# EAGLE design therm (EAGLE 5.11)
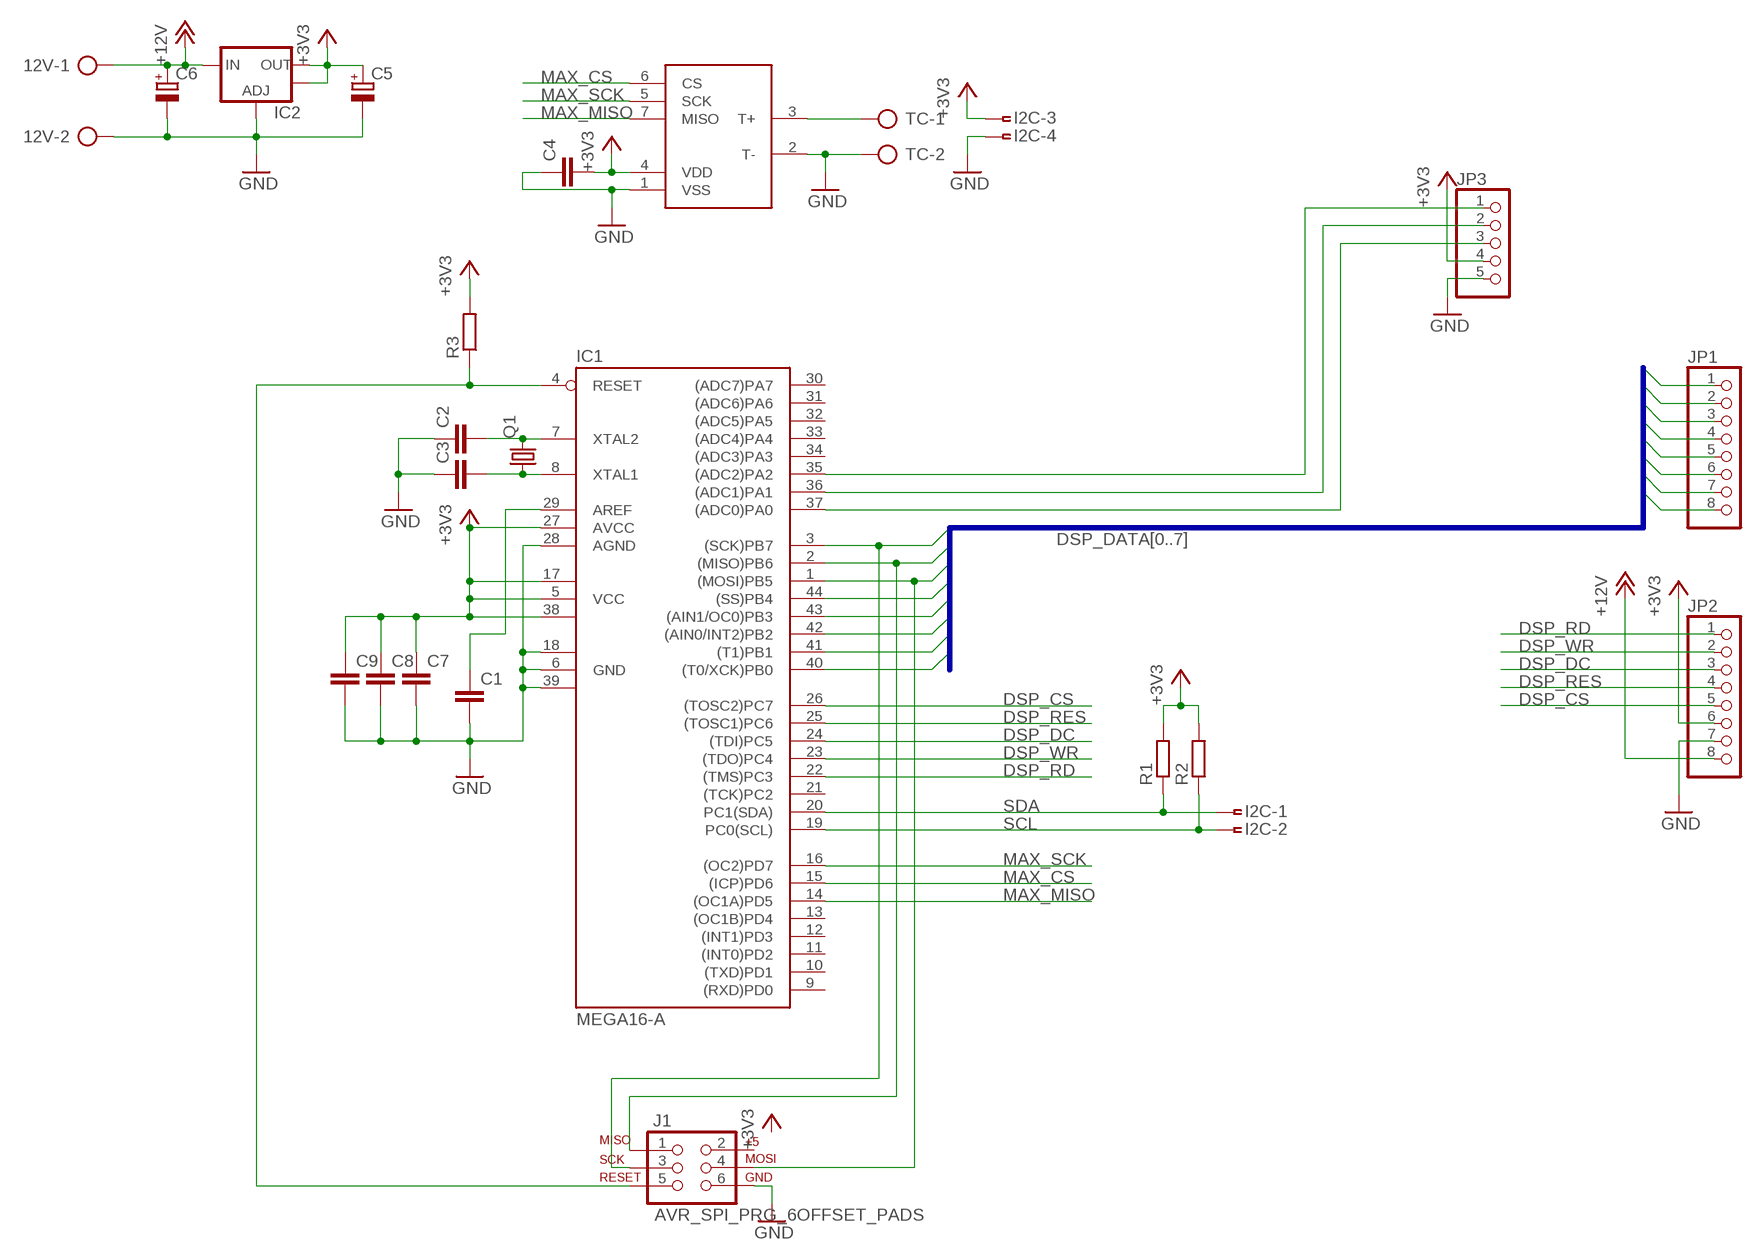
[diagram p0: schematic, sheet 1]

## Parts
12V  AK500/2  [AK500/2]
C1  C-EUC0603  [C0603]
C2  C-EUC0603  [C0603]
C3  C-EUC0603  [C0603]
C4  C-EUC0603  [C0603]
C5  CPOL-EU153CLV-0405  [153CLV-0405]
C6  CPOL-EU153CLV-0405  [153CLV-0405]
C7  C-EUC0603  [C0603]
C8  C-EUC0603  [C0603]
C9  C-EUC0603  [C0603]
I2C  SMDTOP-4  [SMDTOP4]
IC1  MEGA16-A  [TQFP44]
IC2  V_REG_LM1117SOT223  [SOT223]
IC3  MAX6675  [SO08]
J1  AVR_SPI_PRG_6OFFSET_PADS  [2X3_OFFSET]
JP1  PINHD-1X8  [1X08]
JP2  PINHD-1X8  [1X08]
JP3  PINHD-1X5/90  [1X05/90]
Q1  CRYSTALHC49U-V  [HC49U-V]
R1  R-EU_R0603  [R0603]
R2  R-EU_R0603  [R0603]
R3  R-EU_R1206  [R1206]
TC  AK500/2  [AK500/2]

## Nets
+3V3: C4.2 C5.+ C7.1 C8.1 C9.1 I2C.3 IC1.5(VCC) IC1.17(VCC1) IC1.27(AVCC) IC1.38(VCC2) IC2.2(OUT) IC2.4(OUT) IC3.4(VDD) JP2.6 JP3.4 R1.2 R2.2 R3.2
+12V: 12V.1 C6.+ IC2.3(IN) JP2.8
DSP_CS: IC1.26((TOSC2)PC7) JP2.5
DSP_DATA0: IC1.3((SCK)PB7) J1.3 JP1.1
DSP_DATA1: IC1.2((MISO)PB6) J1.1 JP1.2
DSP_DATA2: IC1.1((MOSI)PB5) J1.4 JP1.3
DSP_DATA3: IC1.44((SS)PB4) JP1.4
DSP_DATA4: IC1.43((AIN1/OC0)PB3) JP1.5
DSP_DATA5: IC1.42((AIN0/INT2)PB2) JP1.6
DSP_DATA6: IC1.41((T1)PB1) JP1.7
DSP_DATA7: IC1.40((T0/XCK)PB0) JP1.8
DSP_DC: IC1.24((TDI)PC5) JP2.3
DSP_RD: IC1.22((TMS)PC3) JP2.1
DSP_RES: IC1.25((TOSC1)PC6) JP2.4
DSP_WR: IC1.23((TDO)PC4) JP2.2
GND: 12V.2 C1.2 C2.1 C3.1 C4.1 C5.- C6.- C7.2 C8.2 C9.2 I2C.4 IC1.6(GND) IC1.18(GND1) IC1.28(AGND) IC1.39(GND2) IC2.1(ADJ) IC3.1(VSS) IC3.2(T-) J1.6 JP2.7 JP3.5 TC.2
MAX_CS: IC1.15((ICP)PD6) IC3.6(CS)
MAX_MISO: IC1.14((OC1A)PD5) IC3.7(MISO)
MAX_SCK: IC1.16((OC2)PD7) IC3.5(SCK)
N$1: C1.1 IC1.29(AREF)
N$2: C2.2 IC1.7(XTAL2) Q1.2
N$3: C3.2 IC1.8(XTAL1) Q1.1
N$6: IC1.35((ADC2)PA2) JP3.1
N$7: IC1.36((ADC1)PA1) JP3.2
N$8: IC1.37((ADC0)PA0) JP3.3
N$9: IC3.3(T+) TC.1
RESET: IC1.4(RESET) J1.5 R3.1
SCL: I2C.2 IC1.19(PC0(SCL)) R2.1
SDA: I2C.1 IC1.20(PC1(SDA)) R1.1
Unconnected: IC1.9((RXD)PD0) IC1.10((TXD)PD1) IC1.11((INT0)PD2) IC1.12((INT1)PD3) IC1.13((OC1B)PD4) IC1.21((TCK)PC2) IC1.30((ADC7)PA7) IC1.31((ADC6)PA6) IC1.32((ADC5)PA5) IC1.33((ADC4)PA4) IC1.34((ADC3)PA3) J1.2

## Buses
DSP_DATA[0..7]

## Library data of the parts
12V TC = con-ptr500:AK500/2: CONNECTOR; OC_FARNELL: unknown; OC_NEWARK: unknown
C1-C4 C7-C9 = rcl:C-EU: CAPACITOR, European symbol
C5 C6 = rcl:CPOL-EU: POLARIZED CAPACITOR, European symbol
I2C = con-amp2:SMDTOP-4: AMP connector
IC1 = avr-6:MEGA16: MICROCONTROLLER 16 Kbytes FLASH 1 kbytes SRAM 512 bytes EEPROM USART 8-channel 10 bit ADC
IC2 = SparkFun:V_REG_LM1117: Voltage Regulator LM1117 Standard adjustable voltage regulator but in SMD form. Spark Fun Electronics SKU : COM-00595
IC3 = max6675:MAX6675
J1 = SparkFun:AVR_SPI_PRG_6: AVR ISP 6 Pin This is the reduced ISP connector for AVR programming. Common on Arduino. This footprint will take up less PCB space and can be used with a 10-pin to 6-pin adapter such as SKU: BOB-08508
JP1 JP2 = pinhead:PINHD-1X8: PIN HEADER
JP3 = pinhead:PINHD-1X5: PIN HEADER
Q1 = crystal:CRYSTAL: CRYSTAL; OC_FARNELL: 1666969; OC_NEWARK: unknown
R1-R3 = rcl:R-EU_: RESISTOR, European symbol

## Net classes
0 default: clearance 0.254 mm

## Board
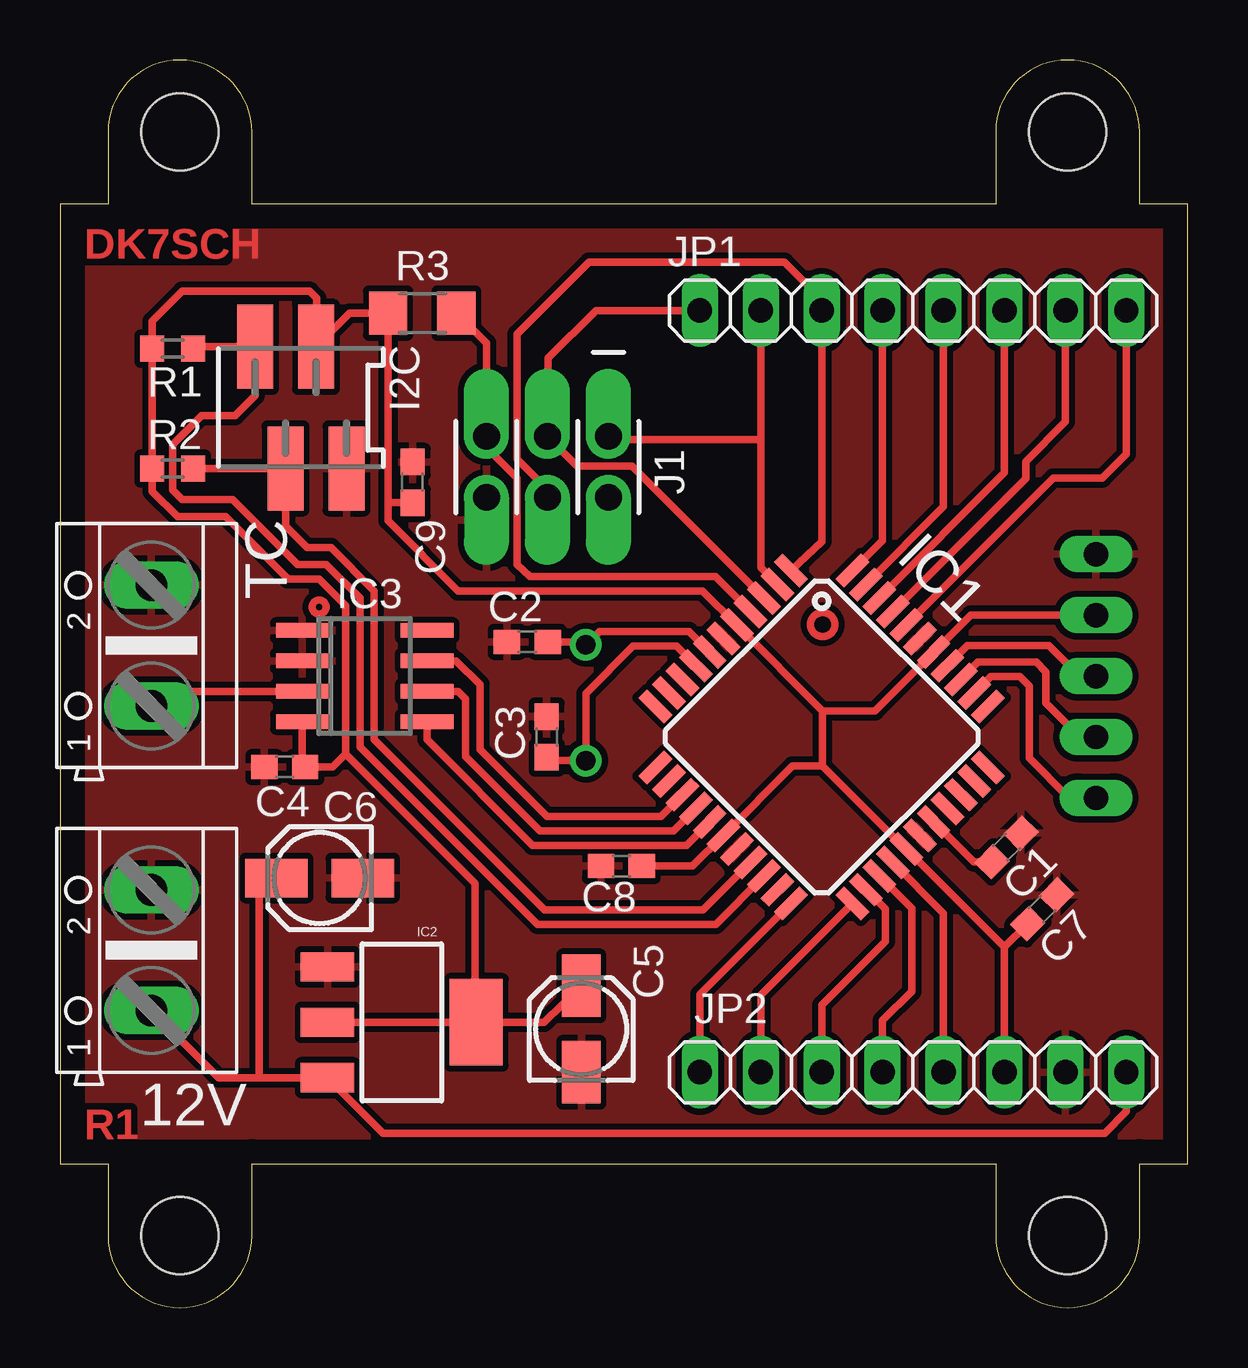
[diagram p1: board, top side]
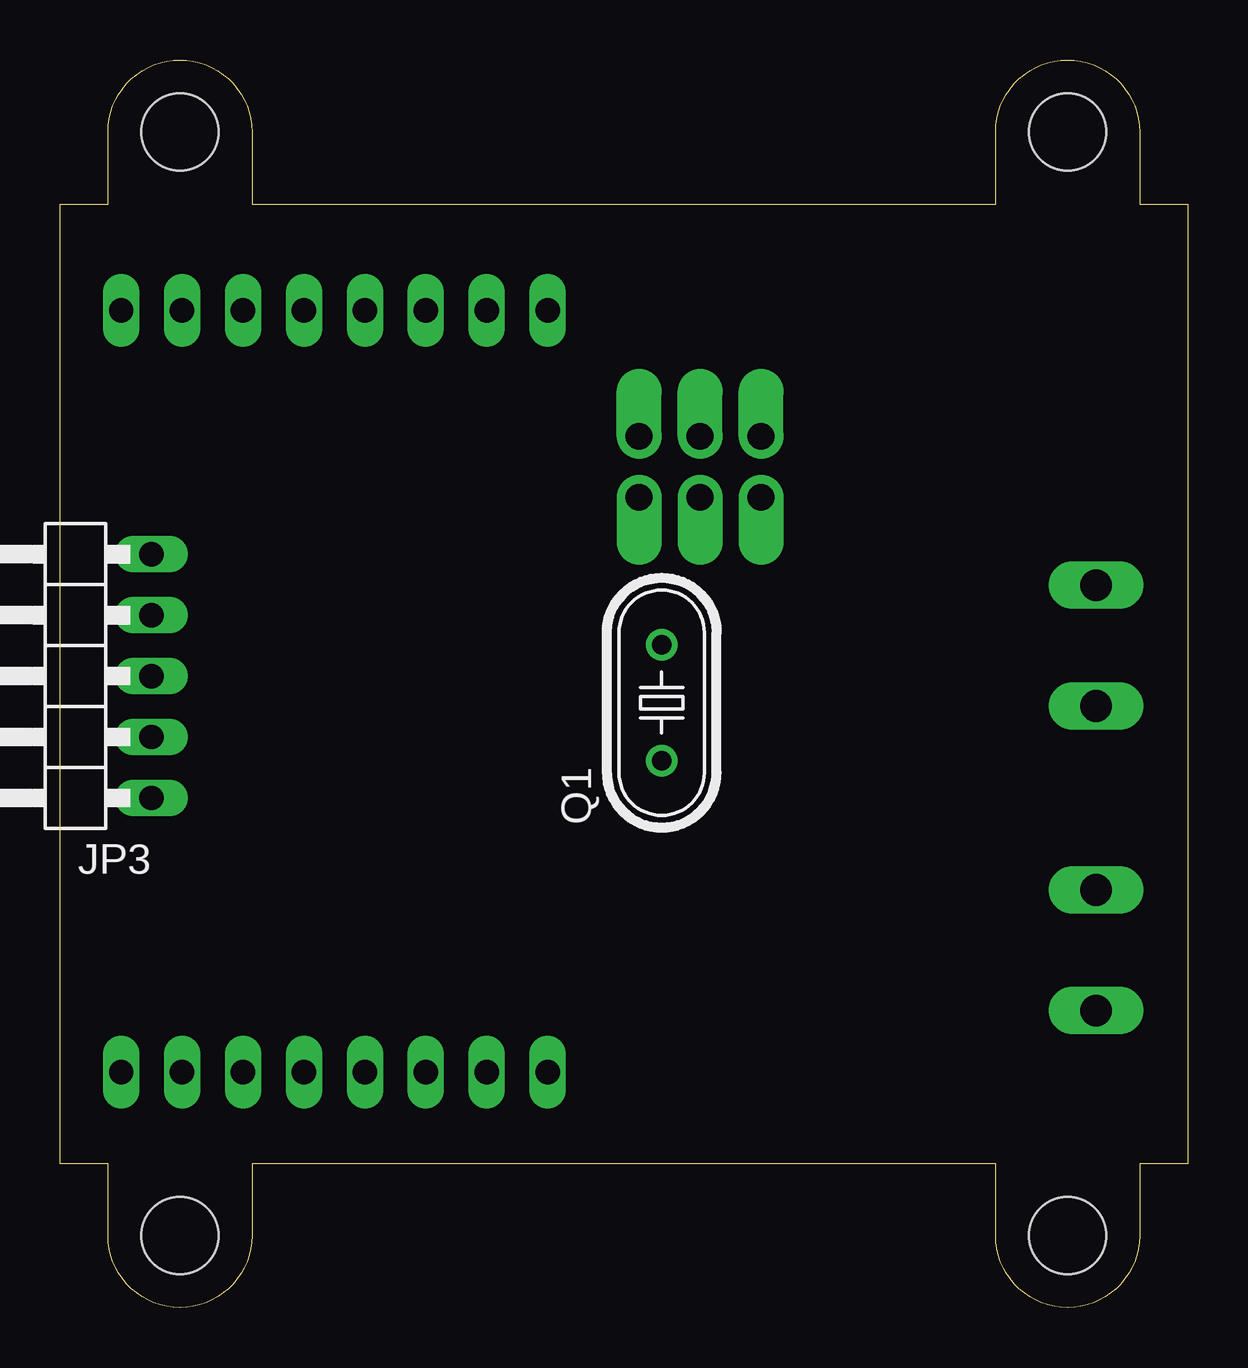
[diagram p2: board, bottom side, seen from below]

Size 47 x 52 mm. Coordinates in mm from the lower left corner, seen from the top.
Outline: 0,6 2,6 2,3 arc90 5,0 arc90 8,3 8,6 39,6 39,3 arc90 42,0 arc90 45,3 45,6 47,6 47,46 45,46 45,49 arc90 42,52 arc90 39,49 39,46 8,46 8,49 arc90 5,52 arc90 2,49 2,46 0,46 0,6
Copper layers (1*16): Top 0.035mm / dielectric 1.5mm / Bottom 0.035mm
Design rules "default": minimum track width 10mil, minimum drill 24mil, track to track 8mil, track to pad 8mil, pad to pad 8mil, via to via 8mil, smd to smd 8mil, copper to edge 40mil, drill to drill 8mil, minimum pad ring 10mil, minimum via ring 8mil, stop-mask expansion 4mil, vias tented up to drill 0mil, thermal gap 10mil
Holes 3.2 mm at 5,3 42,3 42,49 5,49
tRestrict: area 2,5 to 8,7; area 39,5 to 45,7; area 39,45 to 45,47; area 2,45 to 8,47

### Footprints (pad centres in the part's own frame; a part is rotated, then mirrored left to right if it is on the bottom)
AK500/2 = drill 1.321 long: 1 -2.515,0; 2 2.515,0
C0603 = smd 1.1 x 1: 1 -0.85,0; 2 0.85,0
153CLV-0405 = smd 2.6 x 1.6: + 1.8,0; - -1.8,0
SMDTOP4 = smd 1.5 x 3.5: 1 -1.905,2.54; 2 -0.635,-2.54; 3 0.635,2.54; 4 1.905,-2.54
TQFP44 = smd 1.5 x 0.5: 1 -5.8,4; 2 -5.8,3.2; 3 -5.8,2.4; 4 -5.8,1.6; 5 -5.8,0.8; 6 -5.8,0; 7 -5.8,-0.8; 8 -5.8,-1.6; 9 -5.8,-2.4; 10 -5.8,-3.2; 11 -5.8,-4; 23 5.8,-4; 24 5.8,-3.2; 25 5.8,-2.4; 26 5.8,-1.6; 27 5.8,-0.8; 28 5.8,0; 29 5.8,0.8; 30 5.8,1.6; 31 5.8,2.4; 32 5.8,3.2; 33 5.8,4 | smd 0.5 x 1.5: 12 -4,-5.8; 13 -3.2,-5.8; 14 -2.4,-5.8; 15 -1.6,-5.8; 16 -0.8,-5.8; 17 0,-5.8; 18 0.8,-5.8; 19 1.6,-5.8; 20 2.4,-5.8; 21 3.2,-5.8; 22 4,-5.8; 34 4,5.8; 35 3.2,5.8; 36 2.4,5.8; 37 1.6,5.8; 38 0.8,5.8; 39 0,5.8; 40 -0.8,5.8; 41 -1.6,5.8; 42 -2.4,5.8; 43 -3.2,5.8; 44 -4,5.8
SOT223 = smd 1.219 x 2.235: 1 -2.311,-3.099; 2 0,-3.099; 3 2.311,-3.099 | smd 3.6 x 2.2: 4 0,3.099
SO08 = smd 0.6 x 2.2: 1 -1.905,-2.6; 2 -0.635,-2.6; 3 0.635,-2.6; 4 1.905,-2.6; 5 1.905,2.6; 6 0.635,2.6; 7 -0.635,2.6; 8 -1.905,2.6
2X3_OFFSET = drill 1.118 pad 1.88 offset: 1 -2.54,-1.27; 2 -2.54,1.27; 3 0,-1.27; 4 0,1.27; 5 2.54,-1.27; 6 2.54,1.27
1X08 = drill 1.016 long: 1 -8.89,0; 2 -6.35,0; 3 -3.81,0; 4 -1.27,0; 5 1.27,0; 6 3.81,0; 7 6.35,0; 8 8.89,0
1X05/90 = drill 1.016 long: 1 -5.08,-3.81; 2 -2.54,-3.81; 3 0,-3.81; 4 2.54,-3.81; 5 5.08,-3.81
HC49U-V = drill 0.813 round: 1 -2.413,0; 2 2.413,0
R0603 = smd 1 x 1.1: 1 -0.85,0; 2 0.85,0
R1206 = smd 1.6 x 1.803: 1 -1.422,0; 2 1.422,0

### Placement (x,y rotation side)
12V  3.81,14.89 90 top
C1  39.45,19.18 45 top
C2  19.48,27.75 0 top
C3  20.29,23.78 270 top
C4  9.37,22.53 0 top
C5  21.73,11.61 90 top
C6  10.82,17.9 180 top
C7  40.94,16.6 45 top
C8  23.4,18.4 180 top
C9  14.7,34.4 90 top
I2C  10.04,37.51 0 top
IC1  31.75,23.78 315 top
IC2  14.25,11.89 270 top
IC3  12.7,26.32 270 top
J1  20.32,35.04 180 top
JP1  35.56,41.56 0 top
JP2  35.56,9.81 0 top
JP3  46.99,26.32 90 bottom
Q1  21.92,25.21 90 bottom
R1  4.7,39.97 180 top
R2  4.7,34.97 180 top
R3  15.1,41.45 180 top
TC  3.81,27.59 90 top

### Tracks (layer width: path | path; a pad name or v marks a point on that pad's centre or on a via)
+3V3
  Top 0.305: IC2.2 IC2.4 | 31.79,24.87 IC1.5 26.79,29.87 16.6,29.87 13.68,32.79 13.68,33.5 13.68,33.55 | 31.79,24.87 31.79,22.57 | 31.79,22.57 35.25,19.11 IC1.27 39.37,15.03 | 31.79,24.87 33.97,24.87 IC1.38 37.96,28.86 JP3.4 | 31.79,22.57 30.54,22.57 IC1.17 26.37,18.4 C8.1 | C5.+ 20.17,11.89 IC2.4 | 11.9,23.07 11.9,29.27 10.8,30.37 9.5,30.37 6.9,32.97 4.9,32.97 3.85,34.02 R2.2 R1.2 3.85,41.12 5.1,42.37 10.4,42.37 10.7,42.07 10.7,40.08 I2C.3 12.07,41.45 R3.2 13.68,33.55 | 11.9,23.07 17.3,17.67 17.3,11.94 IC2.4 | IC3.4 10.1,22.65 C4.2 11.36,22.53 11.9,23.07 | 39.37,15.03 JP2.6 | C7.1 | 39.37,15.03 C7.1 | 13.68,33.55 C9.1
+12V
  Top 0.305: JP2.8 44.45,8.17 43.55,7.27 13.46,7.27 IC2.3 8.3,9.58 | 3.8,12.37 12V.1 6.61,9.58 8.3,9.58 | C6.+ 8.3,17.18 8.3,9.58
DSP_CS
  Top 0.305: IC1.26 36.83,16.44 JP2.5
DSP_DATA0
  Top 0.305: JP1.1 22.34,41.56 20.35,39.57 20.35,36.34 J1.3 21.55,35.07 23.85,35.07 IC1.3
DSP_DATA1
  Top 0.305: IC1.2 29.21,30.84 29.21,36.17 | 29.21,36.17 JP1.2 | J1.1 23,36.17 29.21,36.17
DSP_DATA2
  Top 0.305: IC1.1 31.75,31.92 JP1.3 31.75,42.02 30.2,43.57 22.05,43.57 19.05,40.57 19.05,35.37 20.32,34.1 J1.4
DSP_DATA3
  Top 0.305: IC1.44 34.29,31.98 JP1.4
DSP_DATA4
  Top 0.305: IC1.43 36.83,33.39 JP1.5
DSP_DATA5
  Top 0.305: IC1.42 39.37,34.79 JP1.6
DSP_DATA6
  Top 0.305: JP1.7 41.91,36.93 40.25,35.27 40.25,34.54 IC1.41
DSP_DATA7
  Top 0.305: JP1.8 44.45,35.57 43.45,34.57 41.41,34.57 IC1.40
DSP_DC
  Top 0.305: IC1.24 34.4,16.6 34.4,15.27 31.75,12.62 JP2.3
DSP_RD
  Top 0.305: IC1.22 26.67,13.04 JP2.1
DSP_RES
  Top 0.305: IC1.25 35.5,16.64 35.5,13.17 34.29,11.96 JP2.4
DSP_WR
  Top 0.305: IC1.23 29.21,13.04 JP2.2
GND
  pour Top: 0,6 47,6 47,46 0,46
MAX_CS
  Top 0.305: IC1.15 25.58,19.87 20,19.87 16.9,22.97 16.9,25.37 16.59,25.68 IC3.6
MAX_MISO
  Top 0.305: IC1.14 25.05,20.47 20.3,20.47 17.5,23.27 17.5,25.97 16.52,26.95 IC3.7
MAX_SCK
  Top 0.305: IC1.16 26.11,19.27 19.7,19.27 15.3,23.67 IC3.5
N$1
  Top 0.305: IC1.29 38.09,18.58 C1.1
N$2
  Top 0.305: IC1.7 26.23,28.17 22.49,28.17 21.94,27.62 Q1.2 21.69,27.75 C2.2
N$3
  Top 0.305: IC1.8 25.7,27.57 23.89,27.57 21.92,25.6 Q1.1 20.42,22.8 C3.2
N$6
  Top 0.305: IC1.35 38.8,26.3 40,26.3 40.4,25.9 40.4,22.9 42.06,21.24 JP3.1
N$7
  Top 0.305: IC1.36 38.26,26.9 40.7,26.9 41.1,26.5 41.1,25.2 42.52,23.78 JP3.2
N$8
  Top 0.305: IC1.37 37.82,27.59 41.21,27.59 42.5,26.3 43.16,26.3 JP3.3
N$9
  Top 0.305: IC3.3 4.42,25.68 TC.1
RESET
  Top 0.305: J1.5 17.81,36.31 | J1.5 17.78,35.84 19.05,34.57 19.05,30.97 19.59,30.47 27.32,30.47 IC1.4 | R3.1 17.78,40.19 J1.5
SCL
  Top 0.305: R2.1 I2C.2 9.4,32.56 10.3,31.67 11.29,31.67 13.1,29.86 13.1,23.67 20.2,16.57 26.8,16.57 IC1.19
SDA
  Top 0.305: R1.1 5.63,40.05 I2C.1 8.13,38.01 7.3,37.17 5.9,37.17 4.7,35.97 4.7,34.07 5.1,33.67 7.2,33.67 9.9,30.97 11.1,30.97 12.5,29.57 12.5,23.37 19.9,15.97 27.33,15.97 IC1.20
(copper drawn outside any net)
  shapes: Top circle x2

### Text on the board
Top: DK7SCH | R1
